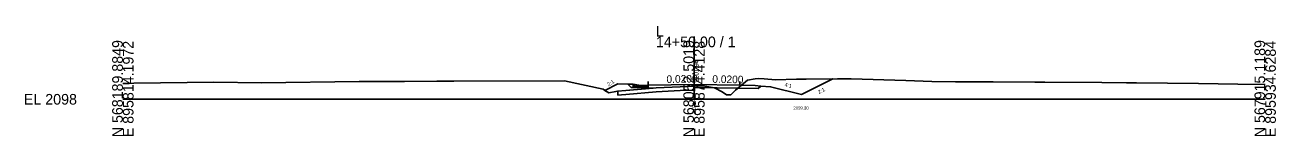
# Model space of a CAD drawing. Extents: x -26 to 1603, y -10 to 13527.
# Drawn here: x -25.7 to 302.8, y 1990.3 to 2019.3 of the extents above; entities that cross this region are included whole.
import ezdxf

# ---------------------------------------------------------------- set-up
doc = ezdxf.new("R2010")
doc.units = 0
for name, color, linetype in [('Default', 7, 'Continuous'), ('Exist XS Center Line Elevation Label', 7, 'Continuous'), ('Exist XS Ground Line', 7, 'Continuous'), ('Old_Level_61', 7, 'Continuous'), ('Old_Level_63', 7, 'Continuous'), ('Prop XS Ditch Slope Text', 7, 'Continuous'), ('Prop XS Ditch Standard Text', 7, 'Continuous'), ('Prop XS Earthwork Shape', 7, 'Continuous'), ('Prop XS EOT Tick Mark', 7, 'Continuous'), ('Prop XS Finish Grade', 7, 'Continuous'), ('Prop XS Finish Grade Earthwork', 7, 'Continuous'), ('Prop XS Finish Grade Paved Shoulder', 7, 'Continuous'), ('Prop XS Finish Grade Pavement', 7, 'Continuous'), ('Prop XS Side Slope Text', 7, 'Continuous'), ('Prop XS Subgrade Earthwork', 7, 'Continuous'), ('Prop XSC Text', 7, 'Continuous'), ('Typical Curb CELL', 7, 'Continuous')]:
    doc.layers.add(name, color=color, linetype=linetype)

msp = doc.modelspace()

# ---------------------------------------------------------------- linework, layer by layer
at = {"layer": 'Exist XS Ground Line'}
for p, q in [((0, 2004.19), (1.68, 2004.18)), ((1.68, 2004.18), (2.91, 2004.25)), ((2.91, 2004.25), (23.92, 2004.47)), ((23.92, 2004.47), (36.45, 2004.35)), ((36.45, 2004.35), (62.07, 2004.67)), ((62.07, 2004.67), (73.98, 2004.66)), ((73.98, 2004.66), (82.46, 2004.78)), ((82.46, 2004.78), (86.93, 2004.79)), ((86.93, 2004.79), (115.99, 2004.83)), ((115.99, 2004.83), (126.17, 2002.63)), ((160.89, 2002.36), (164.09, 2005.06)), ((164.09, 2005.06), (166.07, 2005.38)), ((166.07, 2005.38), (166.97, 2005.51)), ((166.97, 2005.51), (168.44, 2005.39)), ((168.44, 2005.39), (171.37, 2005.16)), ((171.37, 2005.16), (176.9, 2005.28)), ((176.9, 2005.28), (179.44, 2005.34)), ((179.44, 2005.34), (187.7, 2005.4)), ((187.7, 2005.4), (189.59, 2005.42)), ((189.59, 2005.42), (191.29, 2005.36)), ((191.29, 2005.36), (205.59, 2004.94)), ((205.59, 2004.94), (212.43, 2004.71)), ((212.43, 2004.71), (218.67, 2004.57)), ((218.67, 2004.57), (222.86, 2004.64)), ((222.86, 2004.64), (228.56, 2004.58)), ((228.56, 2004.58), (239.54, 2004.52)), ((239.54, 2004.52), (242.1, 2004.5)), ((242.1, 2004.5), (257.09, 2004.39)), ((257.09, 2004.39), (263.62, 2004.33)), ((263.62, 2004.33), (266.22, 2004.3)), ((266.22, 2004.3), (282.46, 2004.15)), ((282.46, 2004.15), (292.79, 2004)), ((126.17, 2002.63), (126.53, 2002.4)), ((126.53, 2002.4), (127.62, 2001.69)), ((127.62, 2001.69), (129.49, 2002.09)), ((129.49, 2002.09), (129.9, 2002.1)), ((129.9, 2002.1), (132.08, 2002.3)), ((132.08, 2002.3), (140.06, 2003)), ((140.06, 2003), (146.37, 2003.28)), ((146.37, 2003.28), (150.03, 2003.42)), ((150.03, 2003.42), (152.25, 2003.54)), ((152.25, 2003.54), (153.33, 2003.39)), ((153.33, 2003.39), (155.38, 2003.02)), ((155.38, 2003.02), (157.42, 2001.93)), ((157.42, 2001.93), (158.57, 2001.19)), ((158.57, 2001.19), (159.66, 2001.19)), ((159.66, 2001.19), (160.89, 2002.36)), ((292.79, 2004), (300, 2003.91))]:
    msp.add_line(p, q, dxfattribs=at)
at = {"layer": 'Old_Level_61'}
for p, q in [((129.99, 2002.11), (129.99, 2001.11)), ((129.99, 2001.11), (131, 2001.2)), ((131, 2001.2), (132.08, 2001.3)), ((132.08, 2001.3), (140.06, 2002)), ((140.06, 2002), (146.37, 2002.28)), ((146.37, 2002.28), (150.03, 2002.42)), ((150.03, 2002.42), (150.17, 2002.43)), ((150.17, 2002.43), (150.17, 2003.43))]:
    msp.add_line(p, q, dxfattribs=at)
at = {"layer": 'Old_Level_63'}
for p, q in [((150, 2000), (150, 2016.53)), ((0, 2000), (150, 2000)), ((150, 2000), (300, 2000))]:
    msp.add_line(p, q, dxfattribs=at)
at = {"layer": 'Prop XS Earthwork Shape'}
for points in [[(178.2, 2001.3), (186.48, 2005.39), (179.44, 2005.34), (176.9, 2005.28), (171.37, 2005.16), (168.44, 2005.39), (166.97, 2005.51), (166.07, 2005.38), (164.09, 2005.06), (161.55, 2002.92), (162, 2002.91), (166.87, 2002.81), (167.57, 2003.5), (170.1, 2003.3)], [(130, 2004.03), (126.62, 2002.34), (127.62, 2001.69), (129.49, 2002.09), (129.9, 2002.1), (132.08, 2002.3), (139.29, 2002.93), (138, 2002.91), (138, 2003.12), (134, 2003.12), (133.5, 2003.11), (132.63, 2003.98)], [(150.17, 2003.14), (150.17, 2003.43), (152.25, 2003.54), (153.33, 2003.39), (155.26, 2003.04)], [(160.89, 2002.36), (161.55, 2002.92), (155.26, 2003.04), (155.38, 2003.02), (157.42, 2001.93), (158.57, 2001.19), (159.66, 2001.19)]]:
    msp.add_lwpolyline(points, close=True, dxfattribs=at)
at = {"layer": 'Prop XS EOT Tick Mark'}
for p, q in [((138, 2003.7), (138, 2004.7)), ((162, 2003.7), (162, 2004.7))]:
    msp.add_line(p, q, dxfattribs=at)
at = {"layer": 'Prop XS Finish Grade'}
for p, q in [((134, 2003.95), (132.63, 2003.98)), ((166.05, 2003.62), (167.57, 2003.5))]:
    msp.add_line(p, q, dxfattribs=at)
at = {"layer": 'Prop XS Finish Grade Earthwork'}
for p, q in [((178.2, 2001.3), (186.48, 2005.39)), ((130, 2004.03), (126.62, 2002.34)), ((132.63, 2003.98), (130, 2004.03)), ((167.57, 2003.5), (170.1, 2003.3)), ((170.1, 2003.3), (178.2, 2001.3))]:
    msp.add_line(p, q, dxfattribs=at)
at = {"layer": 'Prop XS Finish Grade Paved Shoulder'}
msp.add_line((162, 2003.7), (166.05, 2003.62), dxfattribs=at)
at = {"layer": 'Prop XS Finish Grade Pavement'}
for p, q in [((138, 2003.7), (150, 2003.94)), ((150, 2003.94), (162, 2003.7))]:
    msp.add_line(p, q, dxfattribs=at)
at = {"layer": 'Prop XS Subgrade Earthwork'}
for p, q in [((133.5, 2003.11), (132.63, 2003.98)), ((133.5, 2003.11), (134, 2003.12)), ((138, 2003.12), (134, 2003.12)), ((138, 2002.91), (138, 2003.12)), ((139.29, 2002.93), (138, 2002.91)), ((150.17, 2003.14), (150.17, 2003.43)), ((162, 2002.91), (150.17, 2003.14)), ((162, 2002.91), (166.87, 2002.81)), ((166.87, 2002.81), (167.57, 2003.5))]:
    msp.add_line(p, q, dxfattribs=at)
at = {"layer": 'Typical Curb CELL'}
for p, q in [((134, 2003.12), (134, 2003.95)), ((136, 2003.62), (134, 2003.95)), ((134, 2003.12), (138, 2003.12)), ((134.04, 2003.57), (134.19, 2003.62)), ((134.17, 2003.53), (134.04, 2003.57)), ((134.19, 2003.62), (134.17, 2003.53)), ((134.71, 2003.49), (134.6, 2003.41)), ((134.6, 2003.41), (134.77, 2003.37)), ((134.77, 2003.37), (134.71, 2003.49)), ((135.45, 2003.54), (135.41, 2003.43)), ((135.41, 2003.43), (135.53, 2003.42)), ((135.53, 2003.42), (135.45, 2003.54)), ((135.96, 2003.49), (135.85, 2003.41)), ((135.85, 2003.41), (136.02, 2003.37)), ((136.02, 2003.37), (135.96, 2003.49)), ((138, 2003.7), (136, 2003.62)), ((136.7, 2003.54), (136.66, 2003.43)), ((136.66, 2003.43), (136.78, 2003.42)), ((136.78, 2003.42), (136.7, 2003.54)), ((137.41, 2003.34), (137.31, 2003.27)), ((137.31, 2003.27), (137.47, 2003.23)), ((137.47, 2003.23), (137.41, 2003.34)), ((137.74, 2003.59), (137.71, 2003.47)), ((137.71, 2003.47), (137.83, 2003.47)), ((137.83, 2003.47), (137.74, 2003.59)), ((138, 2003.12), (138, 2003.7))]:
    msp.add_line(p, q, dxfattribs=at)
for centre in [(134.07, 2003.66), (134.16, 2003.38), (134.18, 2003.83), (134.25, 2003.28), (134.28, 2003.43), (134.38, 2003.8), (134.54, 2003.46), (134.56, 2003.41), (134.73, 2003.33), (134.75, 2003.73), (134.76, 2003.43), (134.95, 2003.21), (134.96, 2003.39), (135, 2003.51), (135.11, 2003.67), (135.13, 2003.48), (135.16, 2003.35), (135.22, 2003.38), (135.27, 2003.25), (135.41, 2003.38), (135.53, 2003.43), (135.57, 2003.58), (135.63, 2003.43), (135.63, 2003.22), (135.72, 2003.38), (135.78, 2003.52), (135.79, 2003.46), (135.81, 2003.41), (135.98, 2003.31), (136.01, 2003.43), (136.09, 2003.23), (136.21, 2003.39), (136.25, 2003.51), (136.3, 2003.47), (136.32, 2003.2), (136.38, 2003.48), (136.41, 2003.35), (136.47, 2003.38), (136.53, 2003.56), (136.64, 2003.21), (136.89, 2003.64), (136.93, 2003.51), (137.13, 2003.28), (137.28, 2003.56), (137.5, 2003.57), (137.57, 2003.34), (137.74, 2003.2), (137.86, 2003.36), (137.9, 2003.6)]:
    msp.add_circle(centre, 0.00802, dxfattribs=at)

# ---------------------------------------------------------------- texts
at = {"layer": 'Default'}
for rotation, p in [(1.1458, (142.79, 2004.29)), (358.8542, (154.79, 2004.35))]:
    msp.add_text('0.0200', height=2, rotation=rotation, dxfattribs=at).set_placement(p)
at = {"layer": 'Exist XS Center Line Elevation Label'}
msp.add_text('2101.42', height=1, rotation=90, dxfattribs=at).set_placement((150.5, 1996.18))
at = {"layer": 'Old_Level_63'}
for s, p in [('L', (140, 2016.53)), ('14+50.00 / 1', (140, 2013.73)), ('EL 2098', (-26, 1998.6))]:
    msp.add_text(s, height=2.8, dxfattribs=at).set_placement(p)
for s, p in [('N 568189.8849', (0, 1990)), ('E 895814.1972', (2.8, 1990)), ('N 568052.5019', (150, 1990)), ('E 895874.4128', (152.8, 1990)), ('N 567915.1189', (300, 1990)), ('E 895934.6284', (302.8, 1990))]:
    msp.add_text(s, height=2.8, rotation=90, dxfattribs=at).set_placement(p)
at = {"layer": 'Prop XS Ditch Slope Text'}
for s, rotation, p in [('2:1', 32.2598, (127.58, 2003.36)), ('4:1', 346.1338, (173.7, 2003.44))]:
    msp.add_text(s, height=1, rotation=rotation, dxfattribs=at).set_placement(p)
at = {"layer": 'Prop XS Ditch Standard Text'}
msp.add_text('2099.30', height=0.8, dxfattribs=at).set_placement((176.11, 1997.3))
at = {"layer": 'Prop XS Side Slope Text'}
msp.add_text('2:1', height=1, rotation=26.2755, dxfattribs=at).set_placement((182.8, 2001.38))
at = {"layer": 'Prop XSC Text'}
msp.add_text(' 2101.94', height=1.2, rotation=90, dxfattribs=at).set_placement((151.2, 2003.94))

doc.saveas('drawing.dxf')
